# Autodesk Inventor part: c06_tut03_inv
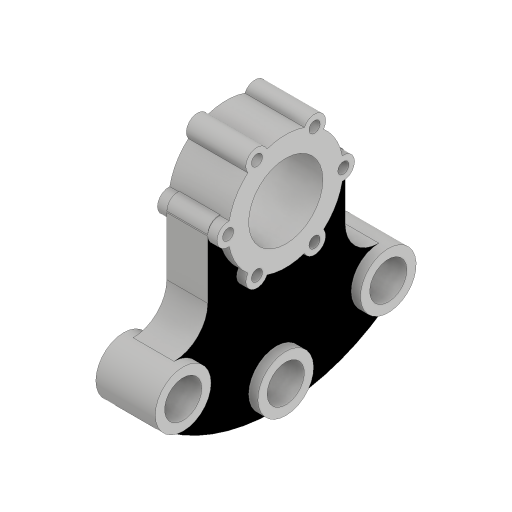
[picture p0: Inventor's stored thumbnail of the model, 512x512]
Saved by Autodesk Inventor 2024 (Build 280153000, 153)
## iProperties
Created: 2015-03
Part Number: c06_tut03_inv
Material: Generic
Document SubType Name: Modeling
Designer: Sandeep
Density: 1 g/cm^3
Appearance: Default
Author: Sandeep
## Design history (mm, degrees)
sketch "Sketch1"
  geometry: L1 (-37, -31.635)-(-37, 0.365); L2 (0, 14.952)-(0, -99.335); L3 (37, 0.365)-(37, -31.635); L4 (-55.203, -64.635)-(-64.945, -76.041); L5 (55.203, -64.635)-(64.945, -76.041); L6 (0, 0)-(41.78, 0); A1 r 31 centre (0, 0) between (30.347, 6.33) and (-30.347, 6.33); A2 r 18 centre (-55, -31.635) between (-55.111, -49.635) and (-37, -31.635); A3 r 15 centre (-55.203, -64.635) between (-55.111, -49.635) and (-64.945, -76.041); A4 r 100 centre (0, 0) between (-64.945, -76.041) and (64.945, -76.041); A5 r 18 centre (55, -31.635) between (37, -31.635) and (55.111, -49.635); A6 r 15 centre (55.203, -64.635) between (64.945, -76.041) and (55.111, -49.635); A7 r 6 centre (-31, 0.365) between (-30.347, 6.33) and (-37, 0.365); A8 r 6 centre (31, 0.365) between (37, 0.365) and (30.347, 6.33); 1 further point
  constraints: 16 point on circle, 12 end point, 8 centre point, 7 tangent, 3 vertical, 2 coincident, 2 symmetric about line, 1 horizontal, 1 parallel, 1 point on line, 3 other
  dimensions: "d0" = 31 radius of A1; "d2" = 18 radius of A5; "d3" = 15 radius of A6; "d4" = 100 radius of A4; "d6" = 81 deg angle of L5 L4; "d7" = 65 vertical distance of L3.start L5.start; "d8" = 6 radius of A7; "d10" = 74 distance between parallel lines of L3 L1
extrude "Extrusion1" new body sketch "Sketch1" stored distance "d11" = 22; taper "d12" = 0 deg
sketch "Sketch5"
  geometry: L1 (0, 48.219)-(0, -124.115); L2 (0, 0)-(43.472, 0); L3 (0, 0)-(17.524, 30.352); A1 r 6 centre (31.011, 0) between (30.42, -5.971) and (30.42, 5.971); A2 r 31 centre (0, 0) between (30.347, 6.33) and (-30.347, 6.33) reference; A3 r 6 centre (15.5, 26.847) between (20.381, 23.358) and (10.038, 29.33); A4 r 31 centre (0, 0) between (30.42, 5.971) and (20.381, 23.358); A5 r 6 centre (-31.011, 0) between (-30.42, 5.971) and (-30.42, -5.971); A6 r 6 centre (-15.5, 26.847) between (-10.038, 29.33) and (-20.381, 23.358); A7 r 6 centre (-15.5, -26.847) between (-20.381, -23.358) and (-10.038, -29.33); A8 r 6 centre (15.5, -26.847) between (10.038, -29.33) and (20.381, -23.358); A9 r 31 centre (0, 0) between (10.038, 29.33) and (-10.038, 29.33); A10 r 31 centre (0, 0) between (-20.381, 23.358) and (-30.42, 5.971); A11 r 31 centre (0, 0) between (-30.42, -5.971) and (-20.381, -23.358); A12 r 31 centre (0, 0) between (-10.038, -29.33) and (10.038, -29.33); A13 r 31 centre (0, 0) between (20.381, -23.358) and (30.42, -5.971); 2 further points
  constraints: 28 point on circle, 12 centre point, 12 symmetric about line, 6 end point, 3 point on line, 1 coincident, 1 horizontal, 1 vertical, 4 other
  dimensions: "d19" = 12 diameter of A1; "d20" = 60 deg angle of L2 L3; "d21" = 12 diameter of A3
extrude "Extrusion2" join sketch "Sketch5" stored distance "d22" = 32; taper "d23" = 0 deg
hole "Hole1" diameter "d26" = 6; stored, may be unused: countersink angle "d30" = 90 deg, drill point angle "d32" = 118 deg; dims "d24" = 10, "d25" = 10, "d27" = 6, "d28" = 4, "d29" = 2, "d31" = 8
pattern_circular "Circular Pattern1" dims angle "d34" = 360 deg
sketch "Sketch6"
  geometry: A1 r 15 centre (-55.203, -64.635) between (-55.111, -49.635) and (-64.945, -76.041) reference; 2 further points
  constraints: 1 coincident, 3 other
extrude "Extrusion3" join sketch "Sketch6" stored distance "d36" = 32; taper "d37" = 0 deg
hole "Hole2" diameter "d40" = 20; stored, may be unused: countersink angle "d44" = 90 deg, drill point angle "d46" = 118 deg; dims "d41" = 6, "d42" = 4, "d43" = 2, "d45" = 8, "d59" = 10, "d60" = 10
pattern_circular "Circular Pattern2" dims angle "d48" = 81 deg
hole "Hole3" diameter "d52" = 40; stored, may be unused: countersink angle "d56" = 90 deg, drill point angle "d58" = 118 deg; dims "d50" = 10, "d51" = 10, "d53" = 6, "d54" = 4, "d55" = 2, "d57" = 8
body "Solid1"
other parameters: "d18" = 62
